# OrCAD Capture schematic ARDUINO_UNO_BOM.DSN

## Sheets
1 COVER: title: PROJECT2; rev: A; company: ORGANIZATION; note: 1234; note: 1234 ENGINEERING WAY
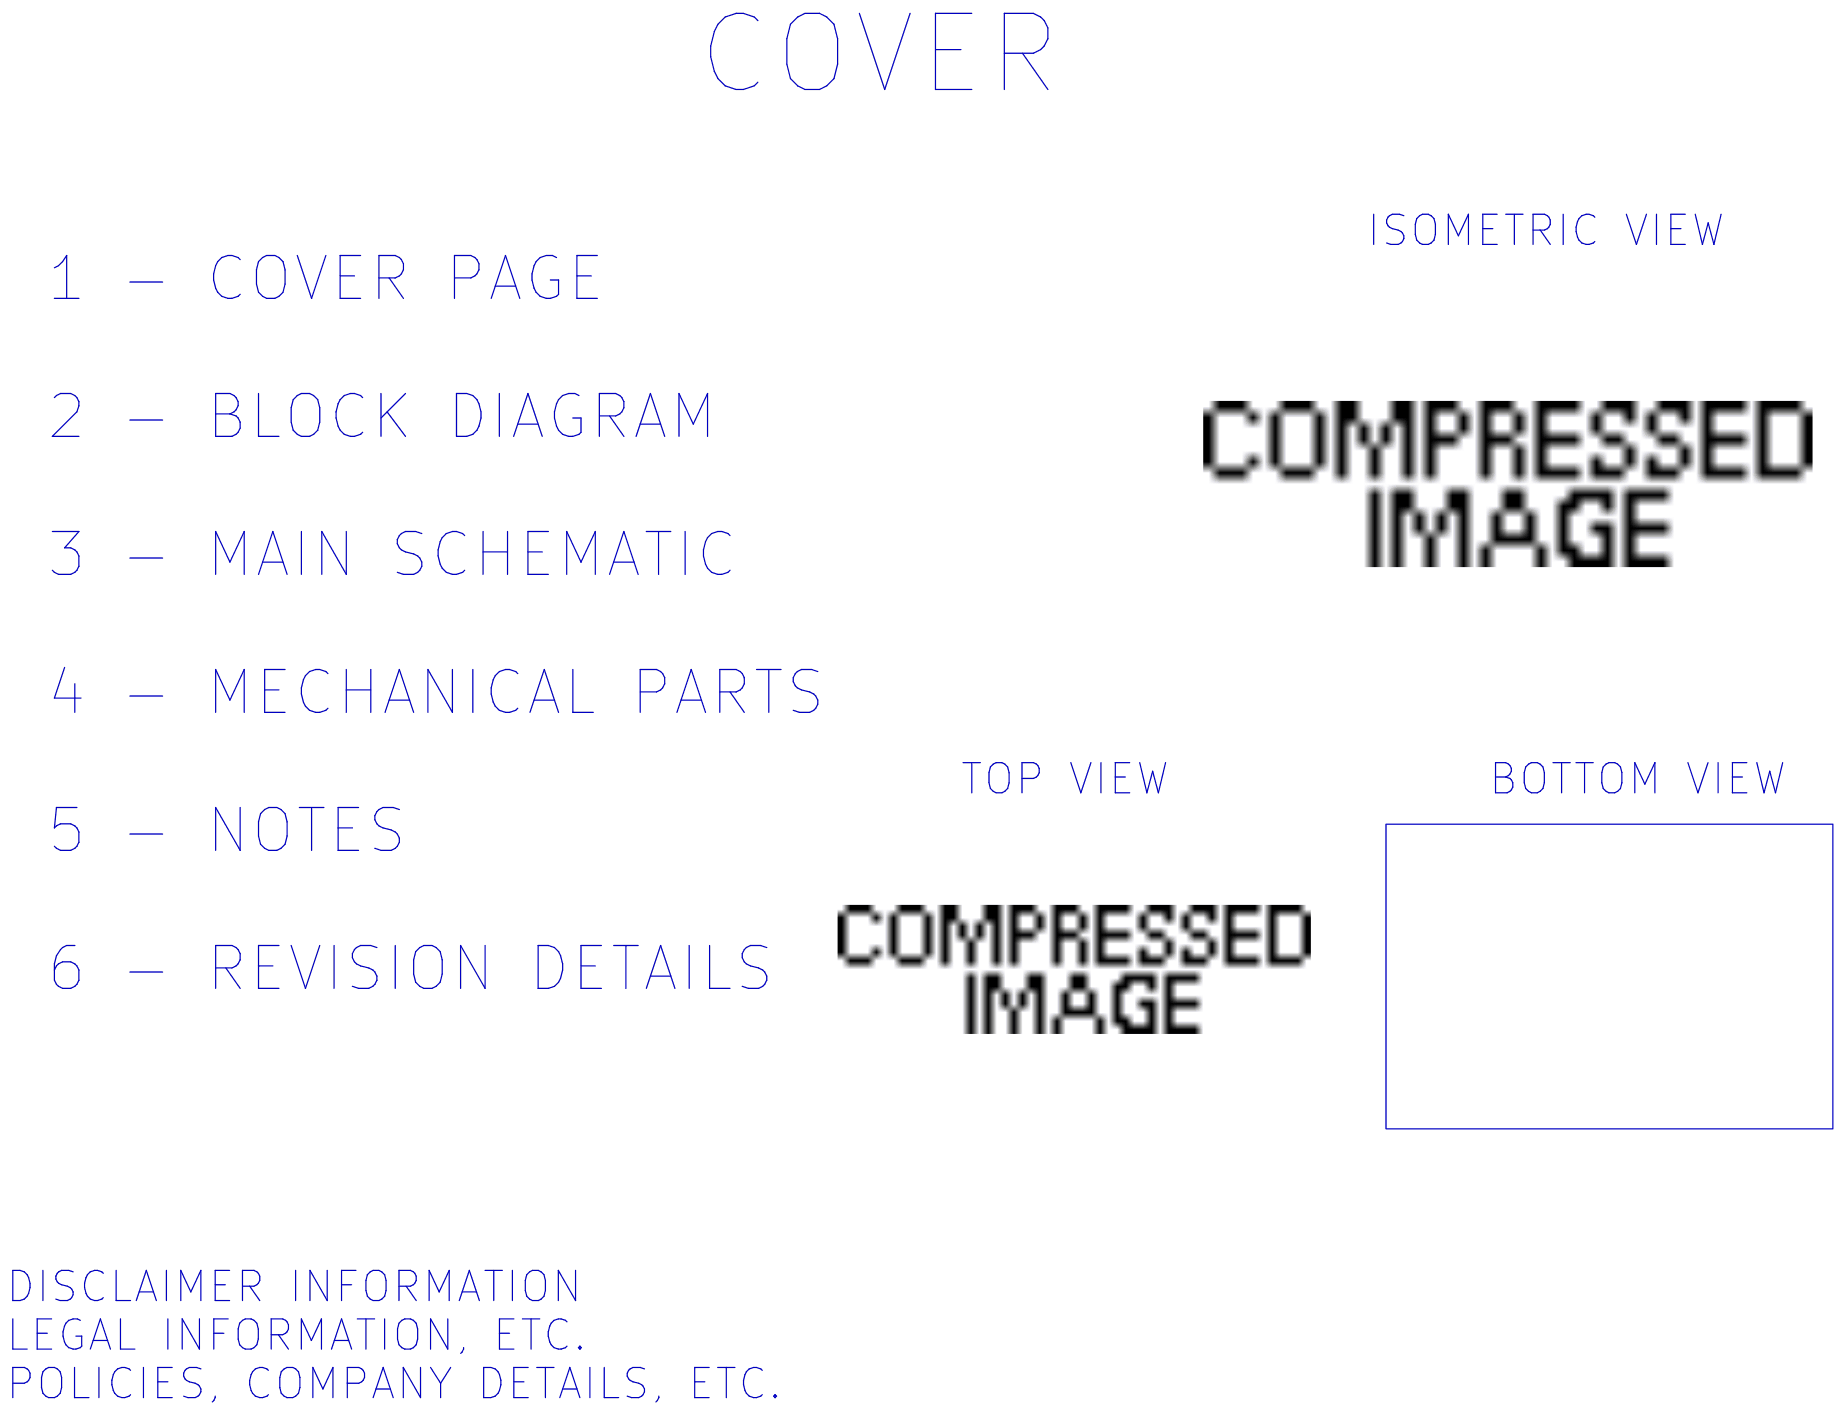
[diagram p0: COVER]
2 BLOCK DIAGRAM
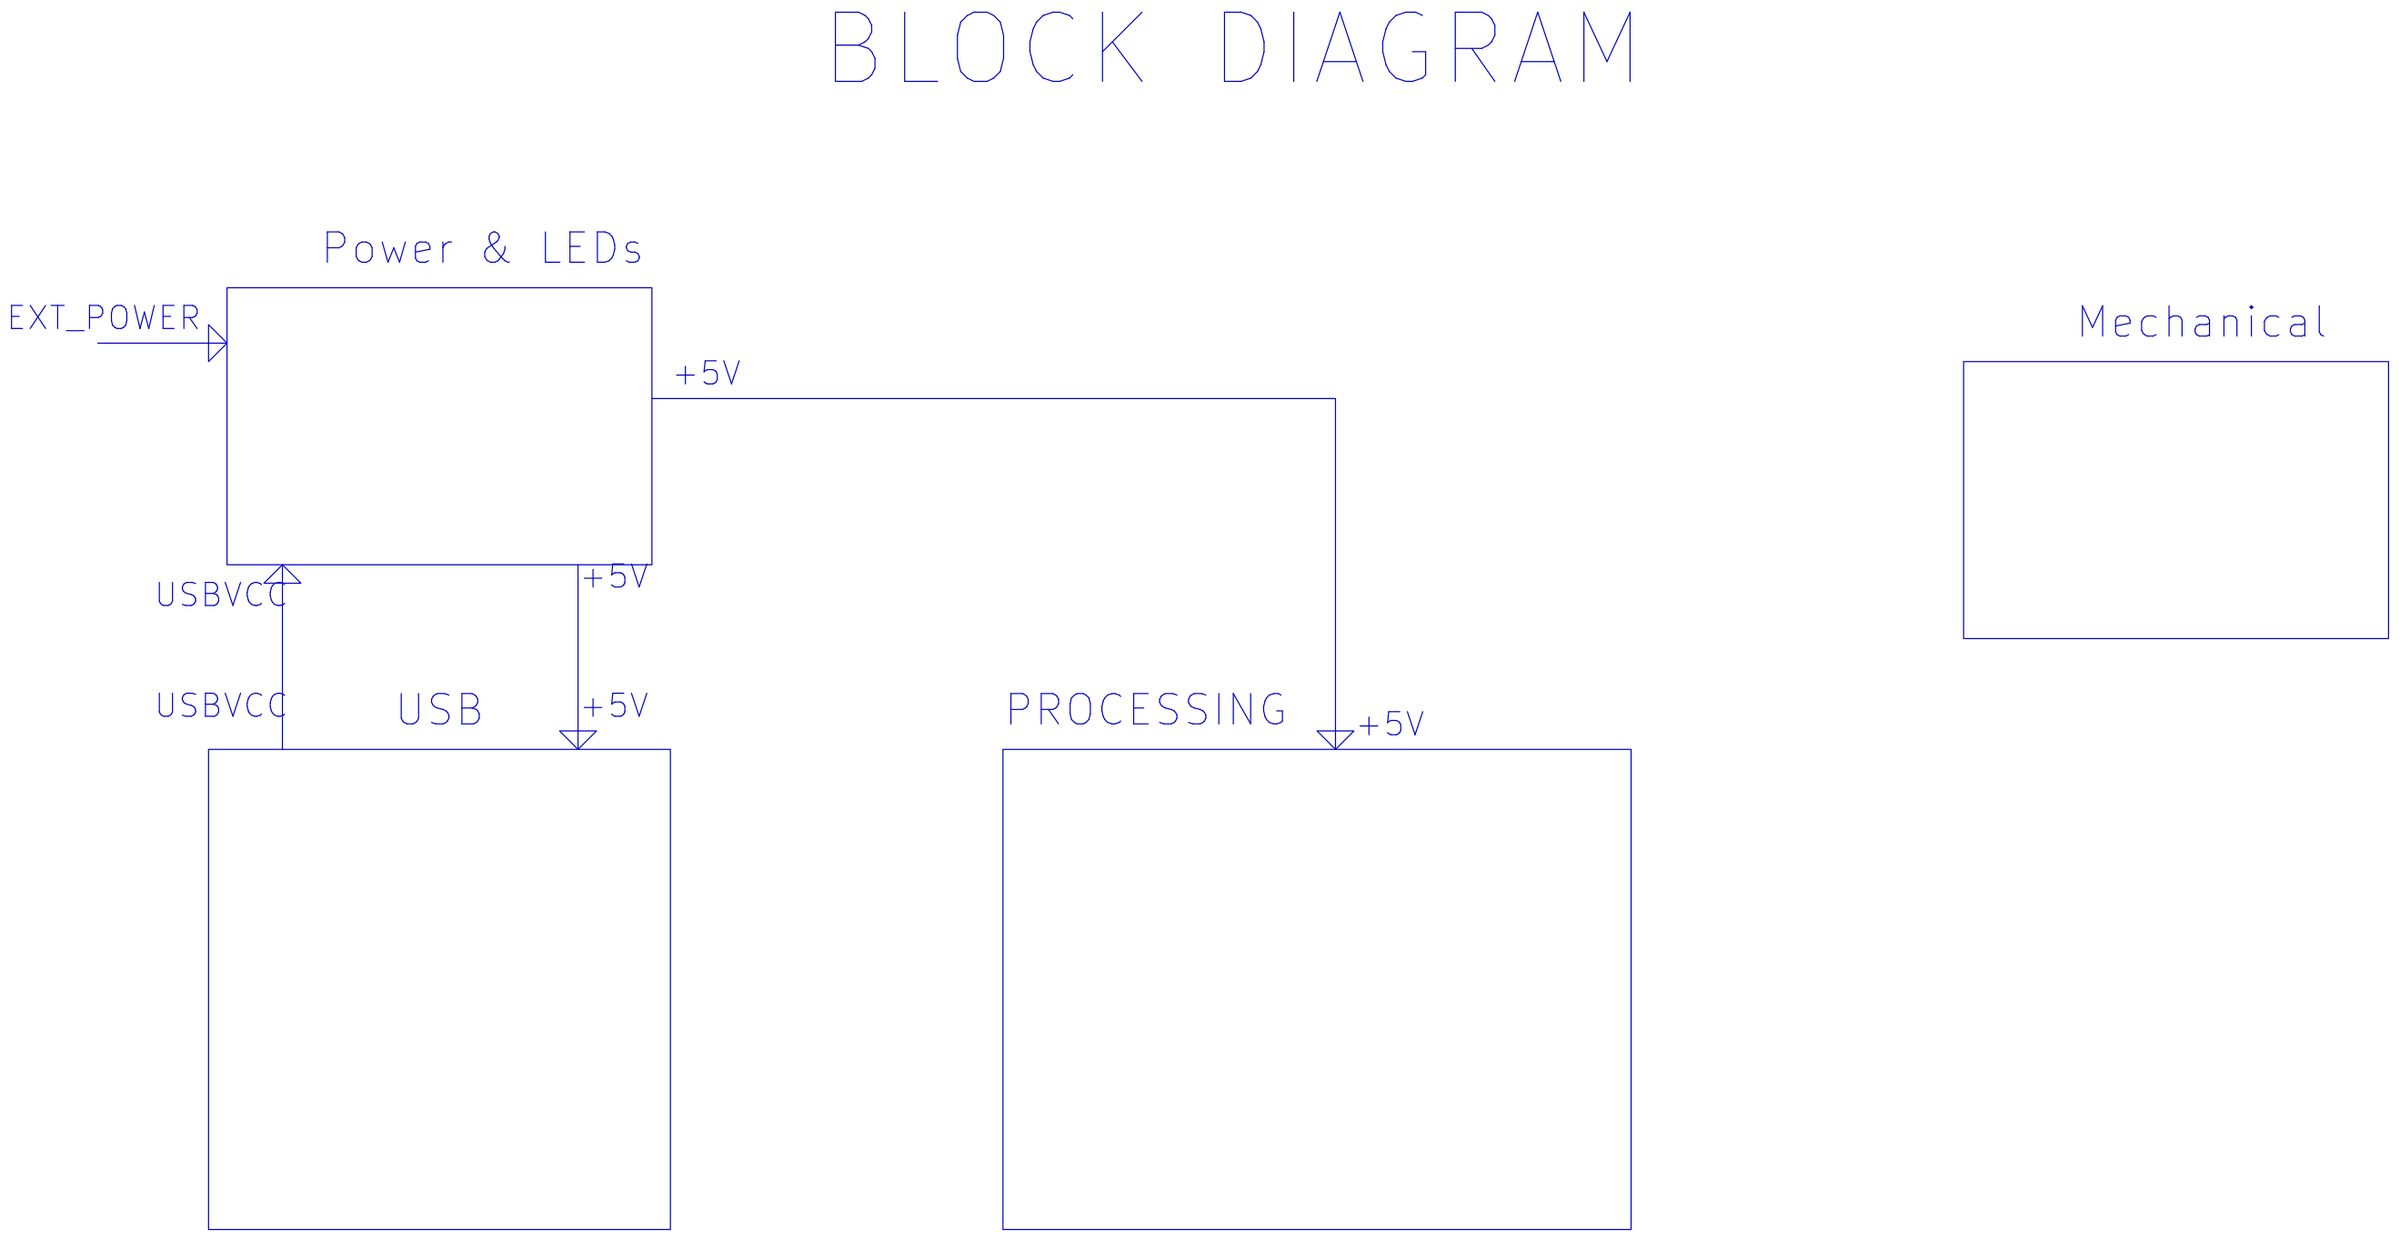
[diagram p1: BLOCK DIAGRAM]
3 MAIN: size D
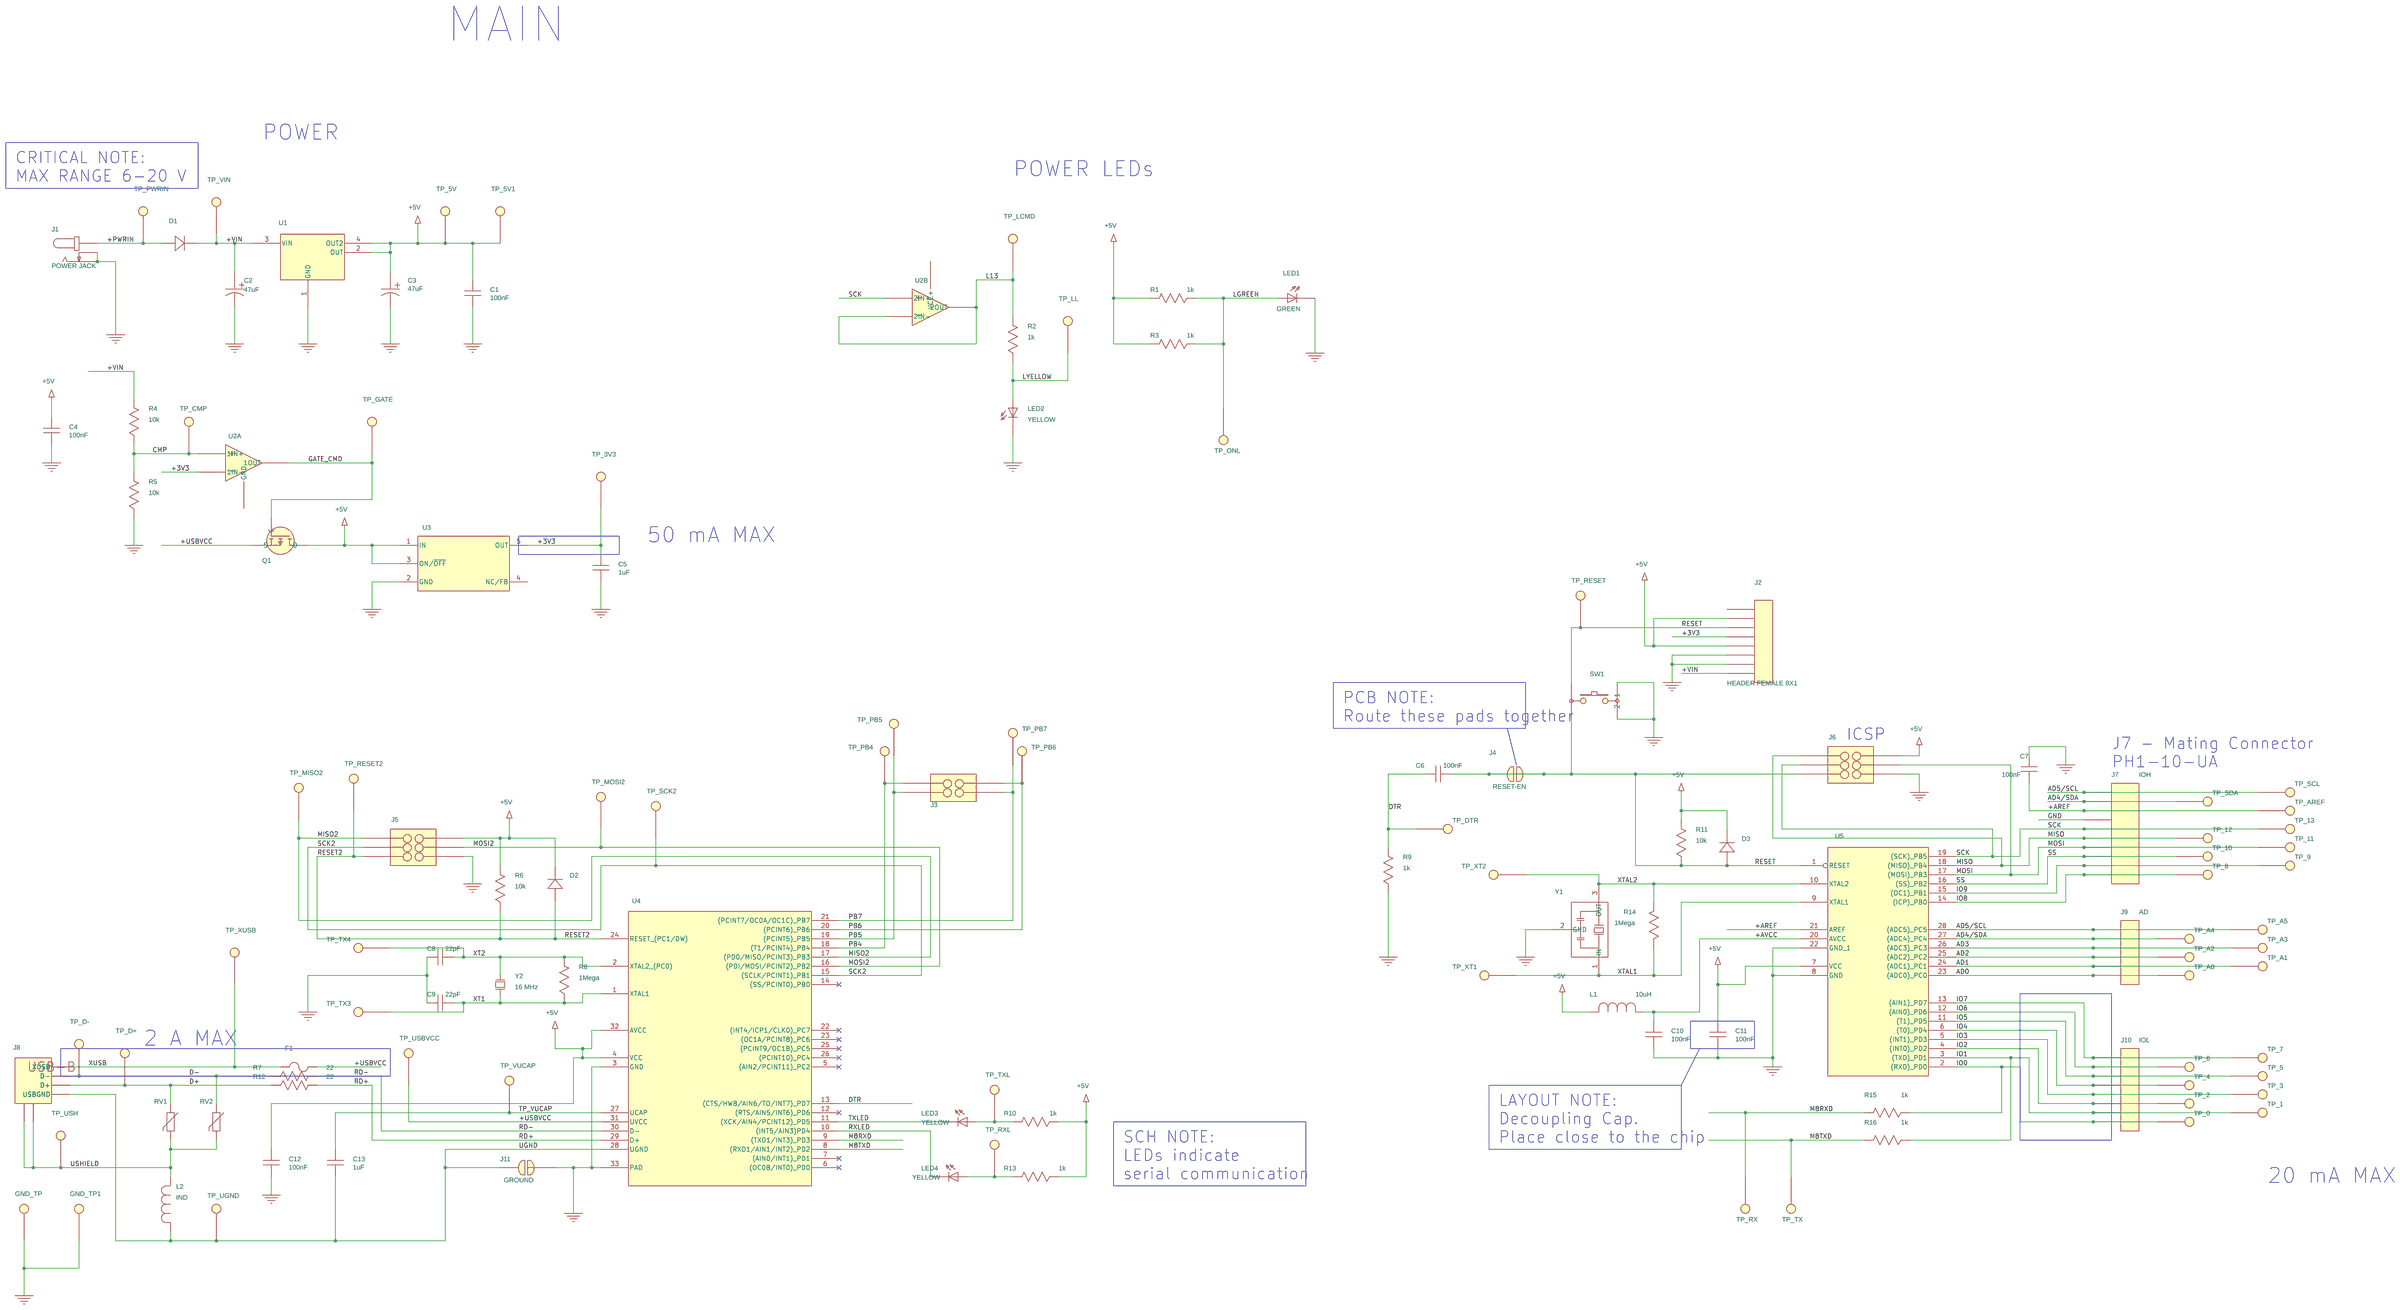
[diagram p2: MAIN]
4 MECHANICAL: size B
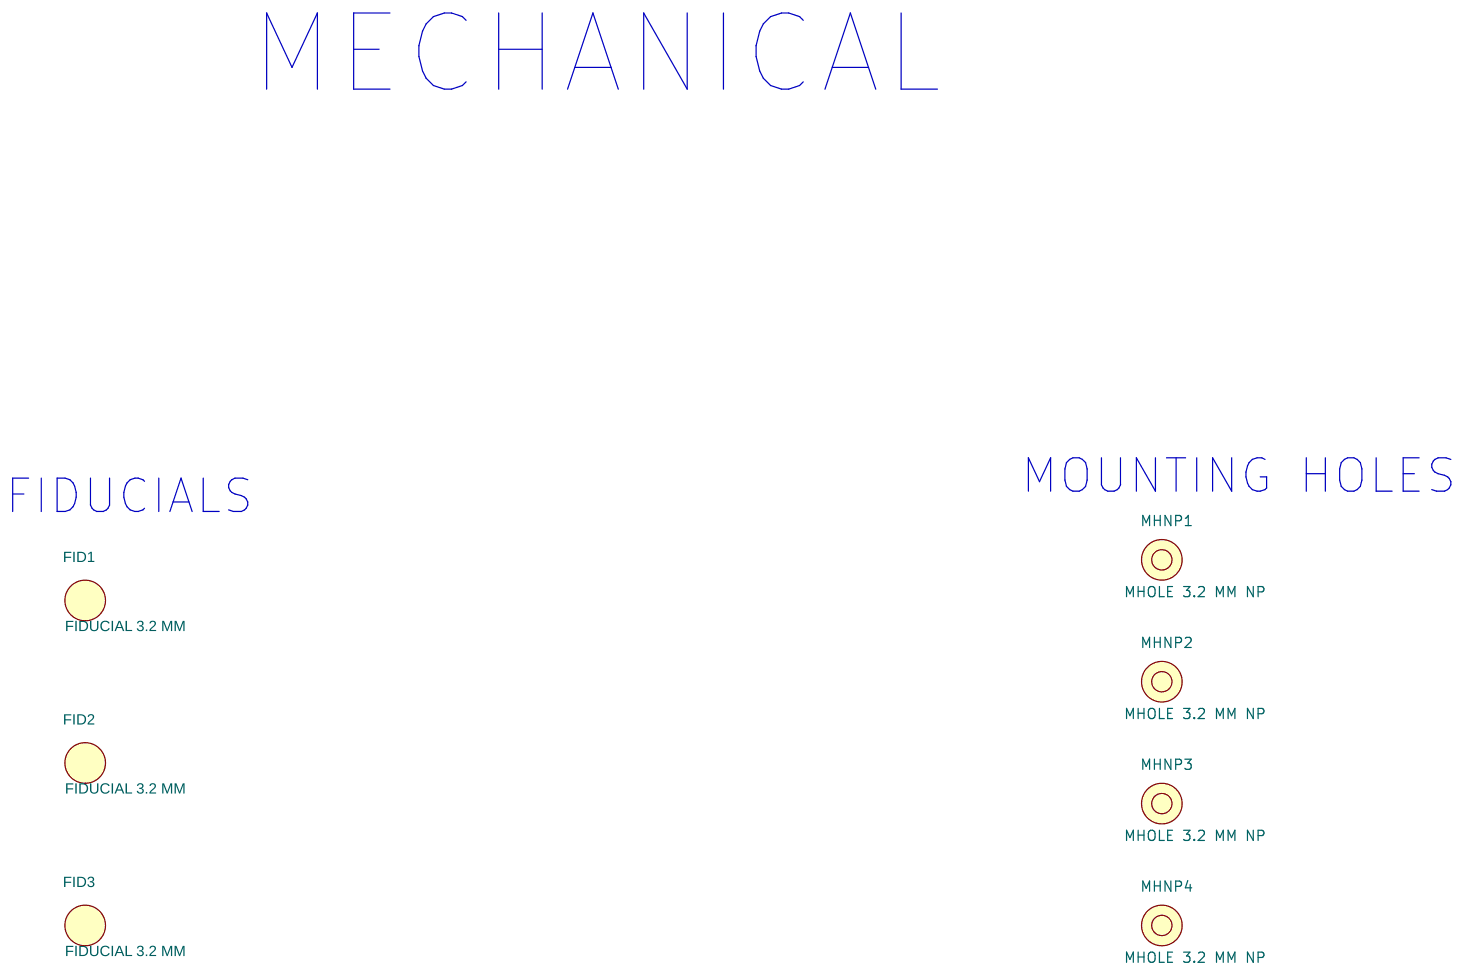
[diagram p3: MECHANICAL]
5 NOTES
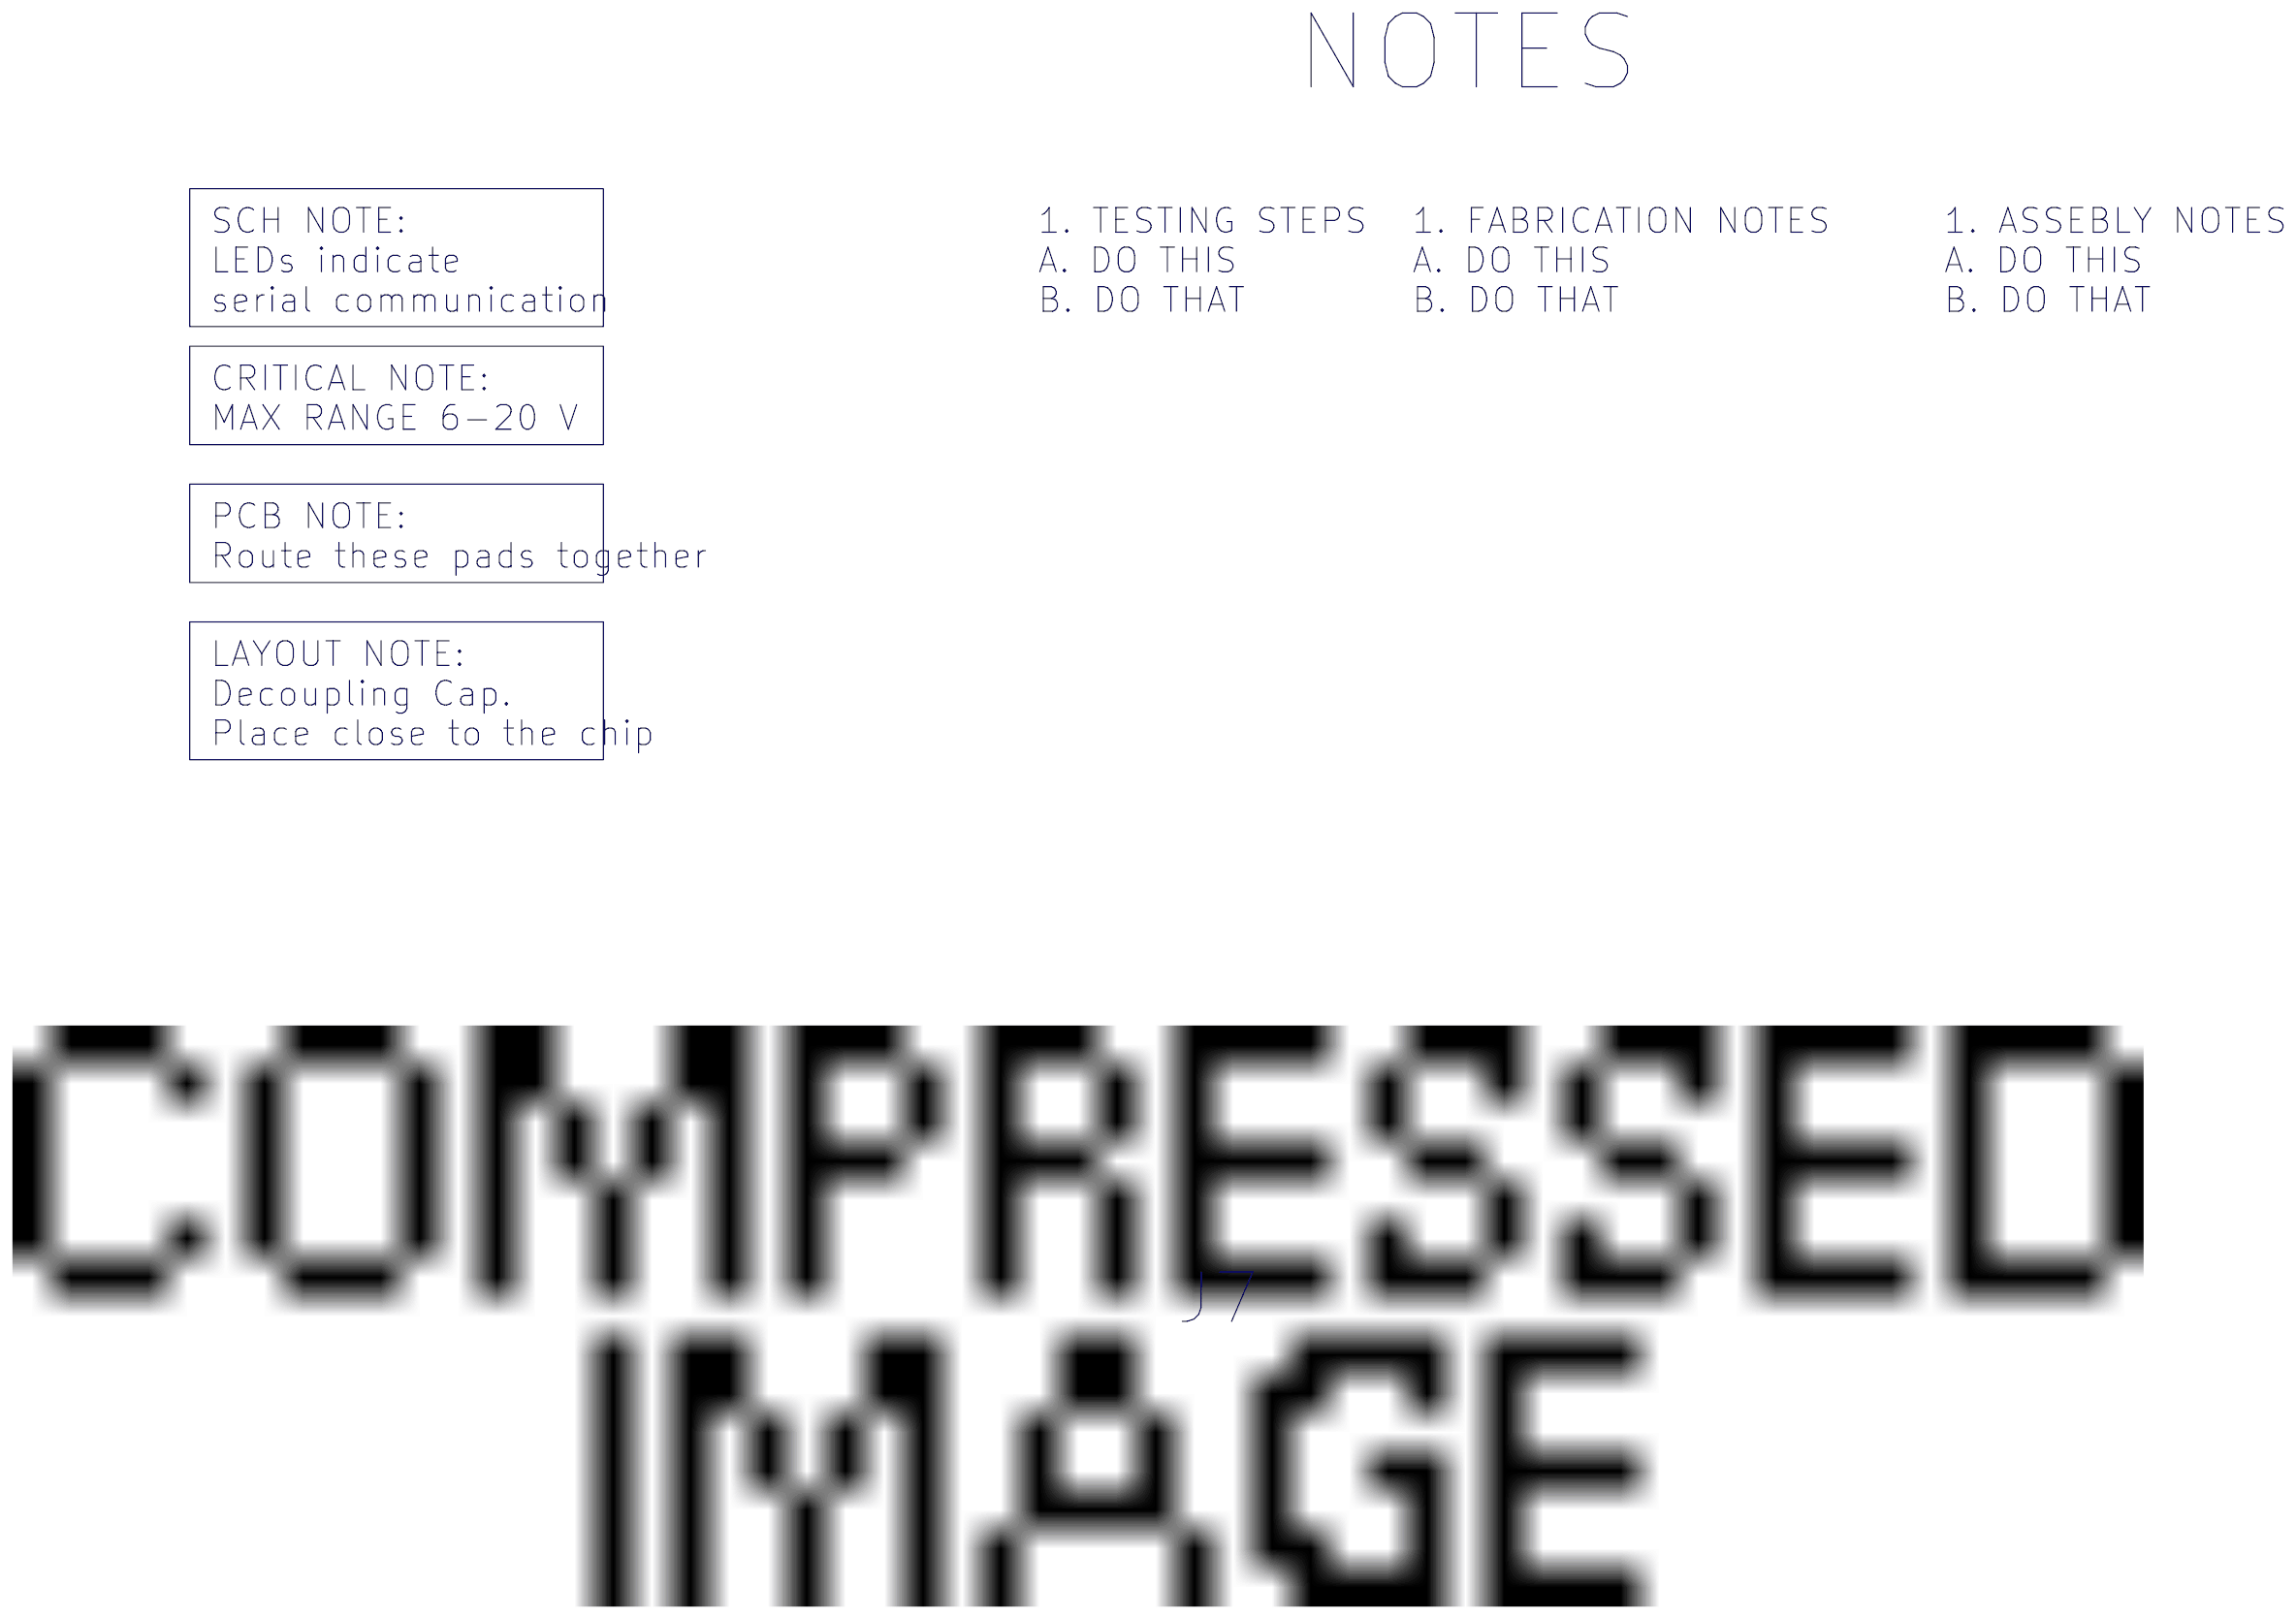
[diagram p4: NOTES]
6 REVISIONS
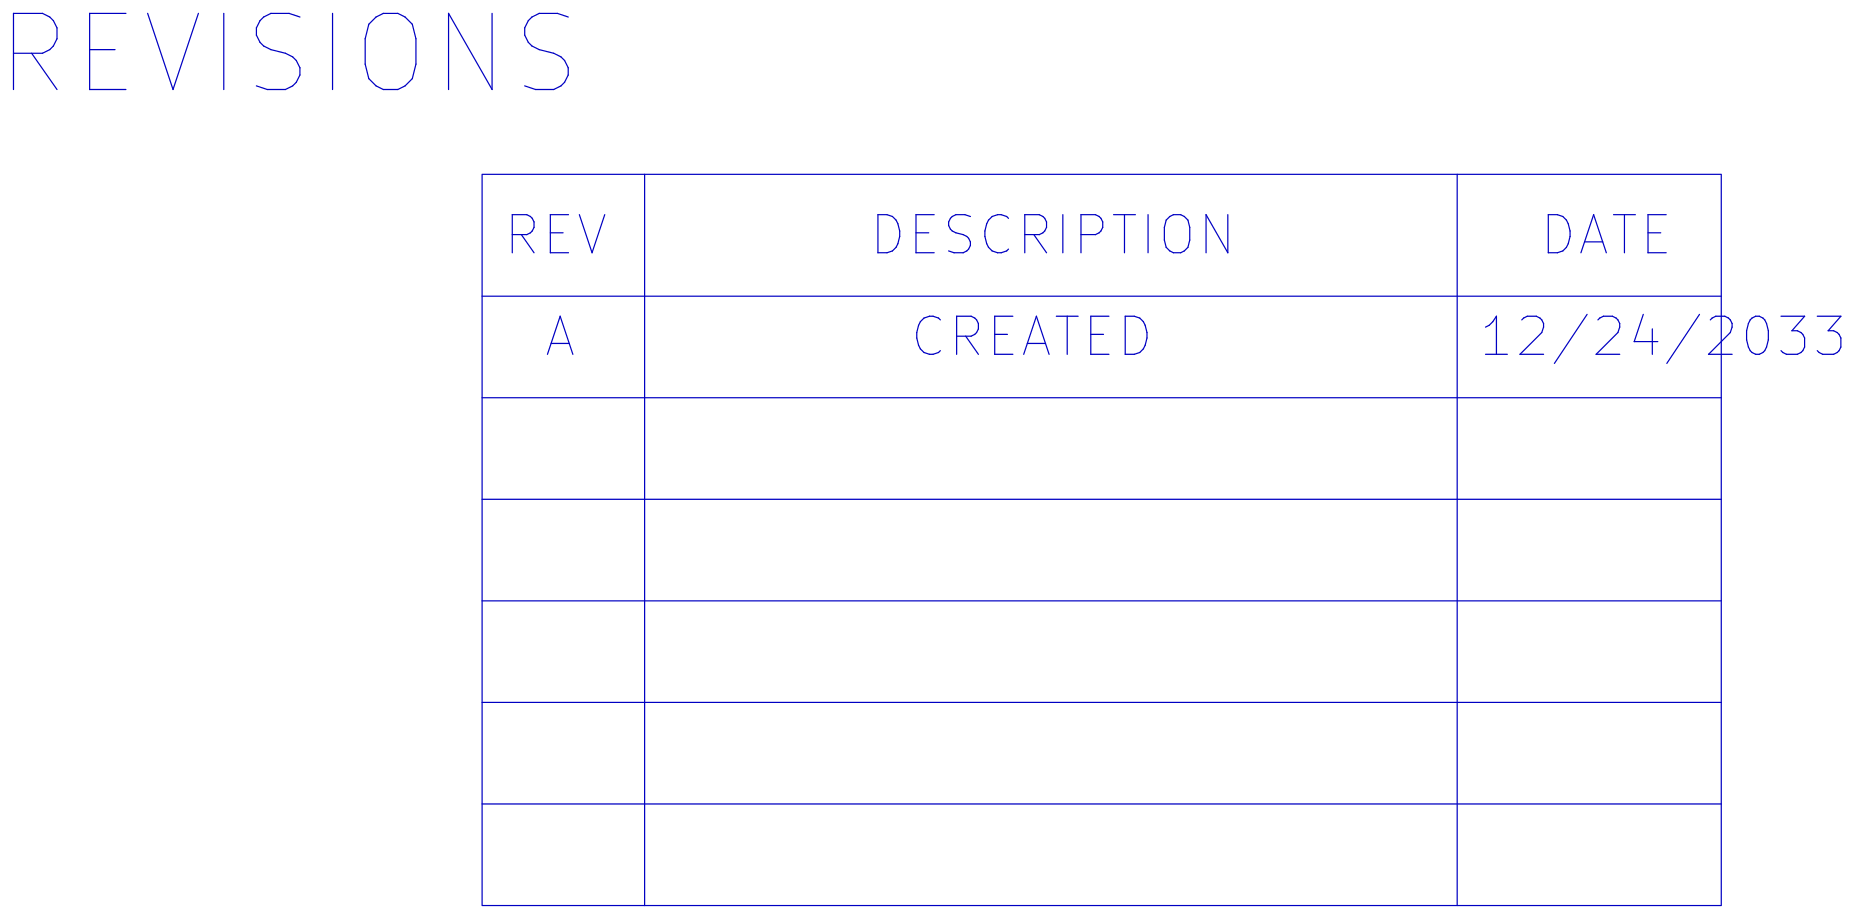
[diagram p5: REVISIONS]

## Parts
sheet MAIN
C1  100nF  [SMC0603]
C2  47uF  [CAP_UCD_6P3X5P8_NCH]
C3  47uF  [CAP_UCD_6P3X5P8_NCH]
C4  100nF  [SMC0603]
C5  1uF  [SMC0603]
C6  100nF  [SMC0603]
C7  100nF  [SMC0603]
C8  22pF  [YAG_CC0603]
C9  22pF  [YAG_CC0603]
C10  100nF  [SMC0603]
C11  100nF  [SMC0603]
C12  100nF  [SMC0603]
C13  1uF  [SMC0603]
D1  DIODE  [ACURN-HF]
D2  DIODE  [ACURN-HF]
D3  DIODE  [ACURN-HF]
F1  MF-MSMF050-2  [FUSE_F050-2]
GND_TP  TEST POINT  [VIA]
GND_TP1  TEST POINT  [VIA]
J1  POWER JACK  [CONN3_PJ-002A_CUI]
J2  HEADER FEMALE 8X1  [conn8_fh]
J3  HEADER 2X2  [headerv_4pos_2x2]
J4  RESET-EN  [jump0510wp]
J5  HEADER 3X2  [hdrv6pos254_2x3]
J6  HEADER 3X2  [hdrv6pos254_2x3]
J7  IOH  [conn10_fh]
J8  UJ2-BH-1-TH  [USB-2-TYPEB_TH]
J9  AD  [conn6_fh]
J10  IOL  [conn8_fh]
J11  GROUND  [jump0510wp]
L1  10uH  [IND_BOURNS_CV201210_B]
L2  IND  [IND_742792040_WRE]
LED1  GREEN  [DIOC200X125X110]
LED2  YELLOW  [DIOC200X125X110]
LED3  YELLOW  [DIOC200X125X110]
LED4  YELLOW  [DIOC200X125X110]
Q1  FDN340P  [SOT-23_ONS]
R1  1k  [SMR0603]
R2  1k  [SMR0603]
R3  1k  [SMR0603]
R4  10k  [STA_RNCP0805_STP]
R5  10k  [STA_RNCP0805_STP]
R6  10k  [STA_RNCP0805_STP]
R7  22  [RES_R0603_ROM]
R8  1Mega  [RES_R0603_ROM]
R9  1k  [SMR0603]
R10  1k  [SMR0603]
R11  10k  [STA_RNCP0805_STP]
R12  22  [RES_R0603_ROM]
R13  1k  [SMR0603]
R14  1Mega  [RES_R0603_ROM]
R15  1k  [SMR0603]
R16  1k  [SMR0603]
RV1  CG0603MLC-05E  [VARISTOR0603]
RV2  CG0603MLC-05E  [VARISTOR0603]
SW1  TL3301NF260QG  [SWITCH_43SMTR92LFS]
TP_0  TEST POINT  [VIA]
TP_1  TEST POINT  [VIA]
TP_2  TEST POINT  [VIA]
TP_3  TEST POINT  [VIA]
TP_3V3  TEST POINT  [VIA]
TP_4  TEST POINT  [VIA]
TP_5  TEST POINT  [VIA]
TP_5V  TEST POINT  [VIA]
TP_5V1  TEST POINT  [VIA]
TP_6  TEST POINT  [VIA]
TP_7  TEST POINT  [VIA]
TP_8  TEST POINT  [VIA]
TP_9  TEST POINT  [VIA]
TP_10  TEST POINT  [VIA]
TP_11  TEST POINT  [VIA]
TP_12  TEST POINT  [VIA]
TP_13  TEST POINT  [VIA]
TP_A0  TEST POINT  [VIA]
TP_A1  TEST POINT  [VIA]
TP_A2  TEST POINT  [VIA]
TP_A3  TEST POINT  [VIA]
TP_A4  TEST POINT  [VIA]
TP_A5  TEST POINT  [VIA]
TP_AREF  TEST POINT  [VIA]
TP_CMP  TEST POINT  [VIA]
TP_D+  TEST POINT  [VIA]
TP_D-  TEST POINT  [VIA]
TP_DTR  TEST POINT  [VIA]
TP_GATE  TEST POINT  [VIA]
TP_LCMD  TEST POINT  [VIA]
TP_LL  TEST POINT  [VIA]
TP_MISO2  TEST POINT  [VIA]
TP_MOSI2  TEST POINT  [VIA]
TP_ONL  TEST POINT  [VIA]
TP_PB4  TEST POINT  [VIA]
TP_PB5  TEST POINT  [VIA]
TP_PB6  TEST POINT  [VIA]
TP_PB7  TEST POINT  [VIA]
TP_PWRIN  TEST POINT  [VIA]
TP_RESET  TEST POINT  [VIA]
TP_RESET2  TEST POINT  [VIA]
TP_RX  TEST POINT  [VIA]
TP_RXL  TEST POINT  [VIA]
TP_SCK2  TEST POINT  [VIA]
TP_SCL  TEST POINT  [VIA]
TP_SDA  TEST POINT  [VIA]
TP_TX  TEST POINT  [VIA]
TP_TX3  TEST POINT  [VIA]
TP_TX4  TEST POINT  [VIA]
TP_TXL  TEST POINT  [VIA]
TP_UGND  TEST POINT  [VIA]
TP_USBVCC  TEST POINT  [VIA]
TP_USH  TEST POINT  [VIA]
TP_VIN  TEST POINT  [VIA]
TP_VUCAP  TEST POINT  [VIA]
TP_XT1  TEST POINT  [VIA]
TP_XT2  TEST POINT  [VIA]
TP_XUSB  TEST POINT  [VIA]
U1  IC REG LINEAR 5V 1A  [SOT223-3_ONS]
U2  MULTIPART IC OPAMP GP 2 CIRCUIT  [DGK8]  (sections A,B)
U3  LP2985-33DBVR  [DBV0005A_N]
U4  ATMEGA16U2-MUR  [32M1-A]
U5  ATMEGA328P-PU  [28P3_ATM]
Y1  AWSCR-16.00CV-T  [AWSCR-MTD_ABR]
Y2  16 MHz  [XTAL_HC49P488W43L1150T466H3]
sheet MECHANICAL
FID1  FIDUCIAL 3.2 MM  [FID32SM16C]
FID2  FIDUCIAL 3.2 MM  [FID32SM16C]
FID3  FIDUCIAL 3.2 MM  [FID32SM16C]
MHNP1  MHOLE 3.2 MM NP  [mtg125]
MHNP2  MHOLE 3.2 MM NP  [mtg125]
MHNP3  MHOLE 3.2 MM NP  [mtg125]
MHNP4  MHOLE 3.2 MM NP  [mtg125]

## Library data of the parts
C1 C4 = CAP_CER_0.1uF_+80%,_-20%_25V_Y5: ROOM: POWER
C2 C3 = CAP_ALUM_47UF_20%_25V_SMD: ROOM: POWER
C5 = CAP_CER_1uF_10%_25V_X5R_0603: ROOM: POWER
C6 C7 C10 C11 = CAP_CER_0.1uF_+80%,_-20%_25V_Y5: ROOM: PROCESSING
C8 C9 = CAP_CER_22PF_5%_50V_0603: ROOM: USB
C12 = CAP_CER_0.1uF_+80%,_-20%_25V_Y5: ROOM: USB
C13 = CAP_CER_1uF_10%_25V_X5R_0603: ROOM: USB
D1 = DIODE_GEN_PURP_400V_1A_1206: ROOM: POWER
D2 = DIODE_GEN_PURP_400V_1A_1206: ROOM: USB
D3 = DIODE_GEN_PURP_400V_1A_1206: ROOM: PROCESSING
F1 = FUSE_PTC_RESET_15V_500MA_1812: ROOM: USB
GND_TP GND_TP1 TP_D+ TP_D- TP_MISO2 TP_MOSI2 TP_PB4-TP_PB7 TP_RESET2 TP_RXL TP_SCK2 TP_TX3 TP_TX4 TP_TXL TP_UGND TP_USBVCC TP_USH TP_VUCAP TP_XUSB = TEST_POINT: ROOM: USB
J1 = CONN_PWR_JACK_2X5.5MM_SOLDER: ROOM: POWER
J2 J10 = RECEPTACLE_STRIP_8P_2.54MM_PITC: ROOM: PROCESSING
J3 = CONN_HEADER_VERT_4POS_2.54MM: ROOM: USB
J4 = SJUMPER1: ROOM: PROCESSING
J5 = CONN_HEADER_VERT_6POS_2.54MM: ROOM: USB
J6 = CONN_HEADER_VERT_6POS_2.54MM: ROOM: PROCESSING
J7 = RECEPTACLE_STRIP_10P_2.54MM_PIT: ROOM: PROCESSING
J8 = CONN_RCPT_USB2.0_TYPEB_4POS_R_A: ROOM: USB
J9 = RECEPTACLE_STRIP_6P_2.54MM_PITC: ROOM: PROCESSING
J11 = SJUMPER1: ROOM: USB
L1 = FIXED_IND_10UH_15MA_1.15_OHM_SM: Manufacturer: Bourns Electronics; ROOM: PROCESSING; Vendor_Part_Number: CV201210-100K
L2 = FERRITE_BEAD_2A_600_OHM_0805: Manufacturer: Wurth Electronics; ROOM: USB; Vendor_Part_Number: 732-1620-1-ND
LED1 = LED_0805_GREEN_2V: ROOM: POWER
LED2 = LED_YELLOW_CLEAR_CHIP_SMD_0805: ROOM: POWER
LED3 LED4 = LED_YELLOW_CLEAR_CHIP_SMD_0805: ROOM: USB
Q1 = MOSFET_P-CH_20V_2A_SSOT3: Manufacturer: ON Semiconductor; ROOM: POWER
R1-R3 = RES_SMD_1K_OHM_1%_1_4W_0603: ROOM: POWER
R4 R5 = RES_10K_OHM_1%_1_4W_0805: ROOM: POWER
R6 = RES_10K_OHM_1%_1_4W_0805: ROOM: USB
R7 R12 = RES_SMD_22_OHM_5%_1_5W_0603: ROOM: USB
R8 = RES_SMD_1M_OHM_1%_1_10W_0603: ROOM: USB
R9 R15 R16 = RES_SMD_1K_OHM_1%_1_4W_0603: ROOM: PROCESSING
R10 R13 = RES_SMD_1K_OHM_1%_1_4W_0603: ROOM: USB
R11 = RES_10K_OHM_1%_1_4W_0805: ROOM: PROCESSING
R14 = RES_SMD_1M_OHM_1%_1_10W_0603: ROOM: PROCESSING
RV1 RV2 = VARISTOR_0603: ROOM: USB
SW1 = SWITCH_TACTILE_SPST-NO_0.05A_12: ROOM: PROCESSING
TP_0-TP_13 TP_A0-TP_A5 TP_AREF TP_DTR TP_RESET TP_RX TP_SCL TP_SDA TP_TX TP_XT1 TP_XT2 = TEST_POINT: ROOM: PROCESSING
TP_3V3 TP_5V TP_5V1 TP_CMP TP_GATE TP_LCMD TP_LL TP_ONL TP_PWRIN TP_VIN = TEST_POINT: ROOM: POWER
U1 = IC_REG_LINEAR_5V_1A_SOT223: ROOM: POWER
U2 = MULTIPART_IC_OPAMP_GP_2_CIRCUIT: ROOM: POWER
U3 = IC_REG_LINEAR_3.3V_150MA_SOT23: ROOM: POWER
U4 = ATMEGA16U2-MUR: ROOM: USB
U5 = ATMEGA328P-PU_1: ROOM: PROCESSING
Y1 = RESONATOR_16MHz: ROOM: PROCESSING
Y2 = CRYSTAL_16.0000MHZ_18PF_T_H: ROOM: USB
FID1-FID3 = FIDUCIAL
MHNP1-MHNP4 = MOUNTING_HOLE_NON-PLATED_3.2_MM

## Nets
+3V3: C5.1 J2.4 TP_3V3.1 U2.2(1IN-) U3.5(OUT)
+5V: C1.1 C3.1 C4.1 C11.1 C12.1 D2.1 D3.1 J2.2 J2.5 J5.2 J6.2 L1.2 Q1.2(D) R1.2 R3.2 R6.2 R10.1 R11.2 R13.1 TP_5V.1 TP_5V1.1 U1.2(OUT) U1.4(OUT2) U3.1(IN) U3.3(ON/~{OFF}) U4.4(VCC) U4.32(AVCC) U5.7(VCC)
+AVCC: C10.1 L1.1 U5.20(AVCC)
+VIN: C2.1 D1.1 J2.8 R4.2 TP_VIN.1 U1.3(VIN)
GND: C1.2 C2.2 C3.2 C4.2 C5.2 C7.1 C8.1 C9.1 C10.2 C11.2 C12.2 GND_TP.1 GND_TP1.1 J1.2 J1.3 J2.6 J2.7 J5.6 J6.6 J7.7 J11.2 LED1.-(K) LED2.-(K) R5.1 R9.1 SW1.1(2) SW1.2(1) U1.1(GND) U2.4(GND) U3.2(GND) U4.3(GND) U4.33(PAD) U5.8(GND) U5.22(GND_1) Y1.2(GND)
VCC+: U2.8(VCC+)
+AREF: C7.2 J7.8 TP_AREF.1 U5.21(AREF)
+PWRIN: D1.2 J1.1 TP_PWRIN.1
+USBVCC: F1.2 Q1.3(S) TP_USBVCC.1 U4.31(UVCC)
AD0: J9.1 TP_A0.1 U5.23((ADC0)_PC0)
AD1: J9.2 TP_A1.1 U5.24((ADC1)_PC1)
AD2: J9.3 TP_A2.1 U5.25((ADC2)_PC2)
AD3: J9.4 TP_A3.1 U5.26((ADC3)_PC3)
AD4/SDA: J7.9 J9.5 TP_A4.1 TP_SDA.1 U5.27((ADC4)_PC4)
AD5/SCL: J7.10 J9.6 TP_A5.1 TP_SCL.1 U5.28((ADC5)_PC5)
CMP: R4.1 R5.2 TP_CMP.1 U2.3(1IN+)
D+: J8.3(D+) R12.1 RV1.1 TP_D+.1
D-: J8.2(D-) R7.1 RV2.1 TP_D-.1
DTR: C6.1 R9.2 TP_DTR.1 U4.13((CTS/HWB/AIN6/TO/INT7)_PD7)
GATE_CMD: Q1.1(G) TP_GATE.1 U2.1(1OUT)
IO0: J10.1 R15.1 TP_0.1 U5.2((RXD)_PD0)
IO1: J10.2 R16.1 TP_1.1 U5.3((TXD)_PD1)
IO2: J10.3 TP_2.1 U5.4((INT0)_PD2)
IO3: J10.4 TP_3.1 U5.5((INT1)_PD3)
IO4: J10.5 TP_4.1 U5.6((T0)_PD4)
IO5: J10.6 TP_5.1 U5.11((T1)_PD5)
IO6: J10.7 TP_6.1 U5.12((AIN0)_PD6)
IO7: J10.8 TP_7.1 U5.13((AIN1)_PD7)
IO8: J7.1 TP_8.1 U5.14((ICP)_PB0)
IO9: J7.2 TP_9.1 U5.15((OC1)_PB1)
L13: R2.2 TP_LCMD.1 U2.6(2IN-) U2.7(2OUT)
LGREEN: LED1.+(A) R1.1 R3.1 TP_ONL.1
LYELLOW: LED2.+(A) R2.1 TP_LL.1
M8RXD: R15.2 TP_RX.1 U4.9((TXD1/INT3)_PD3)
M8TXD: R16.2 TP_TX.1 U4.8((RXD1/AIN1/INT2)_PD2)
MISO: J6.1 J7.5 TP_12.1 U5.18((MISO)_PB4)
MISO2: J5.1 TP_MISO2.1 U4.17((PD0/MISO/PCINT3)_PB3)
MOSI: J6.4 J7.4 TP_11.1 U5.17((MOSI)_PB3)
MOSI2: J5.4 TP_MOSI2.1 U4.16((PDI/MOSI/PCINT2)_PB2)
PB4: J3.1 TP_PB4.1 U4.18((T1/PCINT4)_PB4)
PB5: J3.3 TP_PB5.1 U4.19((PCINT5)_PB5)
PB6: J3.2 TP_PB6.1 U4.20((PCINT6)_PB6)
PB7: J3.4 TP_PB7.1 U4.21((PCINT7/OC0A/OC1C)_PB7)
RD+: R12.2 U4.29(D+)
RD-: R7.2 U4.30(D-)
RESET: C6.2 D3.2 J2.3 J4.1 J4.2 J6.5 R11.1 SW1.3 SW1.4 TP_RESET.1 U5.1(RESET)
RESET2: D2.2 J5.5 R6.1 TP_RESET2.1 U4.24(RESET_(PC1/DW))
RXLED: LED4.-(K) U4.10((INT5/AIN3)PD4)
SCK: J6.3 J7.6 TP_13.1 U2.5(2IN+) U5.19((SCK)_PB5)
SCK2: J5.3 TP_SCK2.1 U4.15((SCLK/PCINT1)_PB1)
SS: J7.3 TP_10.1 U5.16((SS)_PB2)
TP_VUCAP: C13.1 TP_VUCAP.1 U4.27(UCAP)
TXLED: LED3.-(K) U4.11((XCK/AIN4/PCINT12)_PD5)
UGND: C13.2 J8.4(USBGND) J11.1 L2.2 TP_UGND.1 U4.28(UGND)
USHIELD: J8.MH1 J8.MH2 L2.1 RV1.2 RV2.2 TP_USH.1
XT1: C9.2 R8.1 TP_TX3.1 U4.1(XTAL1) Y2.1
XT2: C8.2 R8.2 TP_TX4.1 U4.2(XTAL2_(PC0)) Y2.2
XTAL1: R14.1 TP_XT1.1 U5.9(XTAL1) Y1.1(IN)
XTAL2: R14.2 TP_XT2.1 U5.10(XTAL2) Y1.3(OUT)
XUSB: F1.1 J8.1(XUSB) TP_XUSB.1
N16118: LED3.+(A) R10.2 TP_TXL.1
N16394: LED4.+(A) R13.2 TP_RXL.1

Not connected (* = marked no-connect by the designer): FID1 1; FID2 1; FID3 1; J2 1; U3 4(NC/FB); U4 5((AIN2/PCINT11)_PC2)* 6((OC0B/INT0)_PD0)* 7((AIN0/INT1)_PD1)* 12((RTS/AIN5/INT6)_PD6)* 14((SS/PCINT0)_PB0)* 22((INT4/ICP1/CLK0)_PC7)* 23((OC1A/PCINT8)_PC6)* 25((PCINT9/OC1B)_PC5)* 26((PCINT10)_PC4)*

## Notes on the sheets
sheet 1
- COVER
- ISOMETRIC VIEW
- 1 - COVER PAGE
  2 - BLOCK DIAGRAM
  3 - MAIN SCHEMATIC
  4 - MECHANICAL PARTS
  5 - NOTES
  6 - REVISION DETAILS
- TOP VIEW
- BOTTOM VIEW
- DISCLAIMER INFORMATION
  LEGAL INFORMATION, ETC.
  POLICIES, COMPANY DETAILS, ETC.
sheet 2
- BLOCK DIAGRAM
- Power & LEDs
- EXT_POWER
- Mechanical
- +5V
- +5V
- USBVCC
- USBVCC
- USB
- +5V
- PROCESSING
- +5V
sheet 3
- MAIN
- POWER
- CRITICAL NOTE:
  MAX RANGE 6-20 V
- POWER LEDs
- 50 mA MAX
- PCB NOTE:
  Route these pads together
- ICSP
- J7 - Mating Connector
  PH1-10-UA
- 2 A MAX
- LAYOUT NOTE:
  Decoupling Cap.
  Place close to the chip
- SCH NOTE:
  LEDs indicate
  serial communication
- 20 mA MAX
sheet 4
- MECHANICAL
- MOUNTING HOLES
- FIDUCIALS
sheet 5
- NOTES
- SCH NOTE:
  LEDs indicate
  serial communication
- 1. TESTING STEPS
  A. DO THIS
  B. DO THAT
- 1. FABRICATION NOTES
  A. DO THIS
  B. DO THAT
- 1. ASSEBLY NOTES
  A. DO THIS
  B. DO THAT
- CRITICAL NOTE:
  MAX RANGE 6-20 V
- PCB NOTE:
  Route these pads together
- LAYOUT NOTE:
  Decoupling Cap.
  Place close to the chip
- J7
sheet 6
- REVISIONS
- REV
- DESCRIPTION
- DATE
- A
- CREATED
- 12/24/2033
